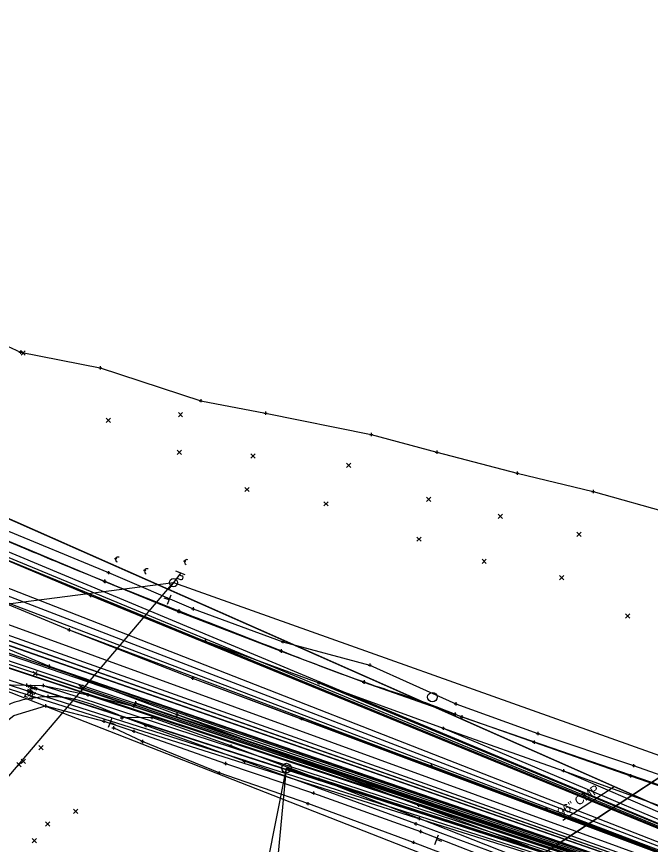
# Model space of a CAD drawing. Extents: x 2331247 to 2333939, y 279314 to 282014.
# Drawn here: x 2332530.2 to 2332730.7, y 280536.5 to 280798.3 of the extents above; entities that cross this region are included whole.
import ezdxf

# ---------------------------------------------------------------- set-up
doc = ezdxf.new("R2010")
doc.units = 0
for name, color, linetype in [('DR_X_Storm_Sewer', 7, 'Continuous'), ('DR_X_Text', 7, 'Continuous'), ('PF_X_Ground_Line', 7, 'Continuous'), ('PV_X_COP', 7, 'Continuous'), ('PV_X_EOP', 7, 'Continuous'), ('PV_X_Shoulder_Aggregate', 7, 'Continuous'), ('RD_X_Cells', 7, 'Continuous'), ('RD_X_GR_Lt', 7, 'Continuous'), ('RW_X_Esmt_SH', 7, 'Continuous'), ('RW_X_Fee_RW', 7, 'Continuous'), ('Stream 1', 7, 'Continuous'), ('SV_Observation', 7, 'Continuous'), ('SV_Setup', 7, 'Continuous'), ('SV_X_Break_Lines', 7, 'Continuous'), ('SV_X_Random_Point', 7, 'Continuous'), ('UT_X_Overhead_Combined', 7, 'Continuous'), ('UT_X_Overhead_Telecom', 7, 'Continuous')]:
    doc.layers.add(name, color=color, linetype=linetype)

msp = doc.modelspace()

# ---------------------------------------------------------------- linework, layer by layer
msp.add_lwpolyline([(2332817.33, 280612.66), (2332607.42, 280474.92)])
at = {"layer": 'DR_X_Storm_Sewer'}
msp.add_line((2332607.42, 280474.92), (2332817.33, 280612.66), dxfattribs=at)
at = {"layer": 'DR_X_Text'}
msp.add_line((2332719.22, 280554.74), (2332702.94, 280544.06), dxfattribs=at)
at = {"layer": 'PF_X_Ground_Line'}
for centre in [(2332661.71, 280583.06), (2332615.53, 280560.63)]:
    msp.add_circle(centre, 1.5, dxfattribs=at)
at = {"layer": 'PV_X_COP'}
msp.add_lwpolyline([(2332444.16, 280650.15), (2332476.96, 280634.44), (2332513.29, 280618.27), (2332546.76, 280604.36), (2332585.85, 280589.05), (2332620.3, 280576.24), (2332661.35, 280561.33), (2332697.65, 280547.71), (2332730.35, 280535.78)], dxfattribs=at)
at = {"layer": 'PV_X_EOP'}
for points in [[(2332450.46, 280661.19), (2332482.6, 280645.87), (2332517.32, 280630.52), (2332553.59, 280615.18), (2332589.86, 280600.74), (2332625.75, 280587.6), (2332665.17, 280573.2), (2332703.16, 280559.78), (2332734.66, 280548.38), (2332773.04, 280534.85)], [(2332438.33, 280638.42), (2332471.73, 280622.52), (2332488.1, 280614.88), (2332507.93, 280606.44), (2332540.43, 280592.84), (2332580.91, 280577.56), (2332615.81, 280564.58), (2332657.37, 280548.85), (2332692.15, 280535.94)], [(2332488.15, 280614.77), (2332487.52, 280613.4), (2332492.44, 280608.51), (2332496.3, 280602.83), (2332499.57, 280597.56), (2332513.01, 280591.6), (2332523.6, 280587.02), (2332533.28, 280586.84), (2332538.59, 280586.73), (2332552.7, 280583.8), (2332567.15, 280580.24), (2332567.76, 280581.26)]]:
    msp.add_lwpolyline(points, dxfattribs=at)
at = {"layer": 'PV_X_Shoulder_Aggregate'}
msp.add_lwpolyline([(2332687.13, 280533.02), (2332657.51, 280544.64), (2332625.77, 280557.07), (2332597.93, 280567.61), (2332572.94, 280576.61), (2332563.48, 280576.47)], dxfattribs=at)
at = {"layer": 'RD_X_Cells'}
for p, q in [((2332533.78, 280585.61), (2332533.39, 280584.69)), ((2332534.71, 280584.67), (2332534.71, 280584.67)), ((2332536.04, 280584.68), (2332535.65, 280583.75))]:
    msp.add_line(p, q, dxfattribs=at)
for points in [[(2332533.98, 280586.09), (2332534.35, 280586.99), (2332535.25, 280586.62)], [(2332533.71, 280582.92), (2332532.81, 280583.3), (2332533.2, 280584.21)], [(2332534.38, 280583.7), (2332534.42, 280583.62), (2332534.44, 280583.57), (2332534.46, 280583.53), (2332534.48, 280583.51), (2332534.52, 280583.47), (2332534.55, 280583.44), (2332534.62, 280583.39), (2332534.65, 280583.37), (2332534.7, 280583.35), (2332534.78, 280583.34), (2332534.84, 280583.33), (2332534.9, 280583.35), (2332534.97, 280583.39), (2332535.02, 280583.43), (2332535.04, 280583.44), (2332535.09, 280583.49), (2332535.32, 280584.06), (2332533.85, 280584.68), (2332533.58, 280584.04), (2332533.59, 280583.94), (2332533.62, 280583.84), (2332533.69, 280583.75), (2332533.78, 280583.67), (2332533.88, 280583.61), (2332533.95, 280583.58), (2332534.03, 280583.58), (2332534.15, 280583.58), (2332534.25, 280583.61), (2332534.38, 280583.7), (2332534.65, 280584.34)], [(2332534.47, 280586.18), (2332535.95, 280585.56), (2332534.25, 280585.64), (2332535.51, 280584.52), (2332534.03, 280585.13)], [(2332535.71, 280586.42), (2332536.61, 280586.05), (2332536.23, 280585.16)], [(2332535.45, 280583.27), (2332535.07, 280582.36), (2332534.18, 280582.73)]]:
    msp.add_lwpolyline(points, dxfattribs=at)
at = {"layer": 'RD_X_GR_Lt'}
for p, q in [((2332671, 280576.81), (2332757.54, 280546.99)), ((2332602.3, 280562.78), (2332571.04, 280574.11)), ((2332656.5, 280542.97), (2332602.3, 280562.78)), ((2332719.13, 280519.92), (2332656.5, 280542.97))]:
    msp.add_line(p, q, dxfattribs=at)
for points in [[(2332284.04, 280768.15), (2332290.4, 280762.4), (2332306.51, 280748.93), (2332330.87, 280733.26), (2332354.16, 280719.6), (2332375.56, 280706.62), (2332399.69, 280693.06), (2332427.39, 280678.53), (2332457.23, 280663.43), (2332489.53, 280649.05), (2332523.64, 280633.83), (2332554.34, 280621.11), (2332584.43, 280609.19), (2332611.78, 280598.56), (2332640.76, 280587.24), (2332660.26, 280581.49), (2332670.28, 280577.06), (2332671, 280576.81)], [(2332571.04, 280574.11), (2332559.55, 280578.28), (2332546.93, 280585.22), (2332522.34, 280581.21), (2332514.24, 280566.6), (2332508.9, 280557.77), (2332507.36, 280555.09)]]:
    msp.add_open_spline(points, degree=3, dxfattribs=at)
at = {"layer": 'RW_X_Esmt_SH'}
for p, q in [((2332582.02, 280622.27), (2332578.33, 280617.27)), ((2332583.51, 280621.69), (2332580.53, 280622.86)), ((2332580.87, 280620.71), (2332581.98, 280620.27)), ((2332581.65, 280621.77), (2332582.44, 280621.46))]:
    msp.add_line(p, q, dxfattribs=at)
for centre, radius in [((2332561.54, 280626.86), 0.2), ((2332583.34, 280626.05), 0.2), ((2332570.72, 280623.14), 0.2), ((2332579.81, 280619.27), 1.3)]:
    msp.add_circle(centre, radius, dxfattribs=at)
for centre, radius, start, end in [((2332562.28, 280626.56), 0.8, 67.9895, 247.9895), ((2332584.09, 280625.76), 0.8, 68.5702, 248.5702), ((2332571.46, 280622.85), 0.8, 68.2799, 248.2799), ((2332582.22, 280620.86), 0.638, 247.4256, 69.6722)]:
    msp.add_arc(centre, radius, start, end, dxfattribs=at)
at = {"layer": 'RW_X_Fee_RW'}
for p, q in [((2332578.97, 280615.29), (2332577.81, 280612.31)), ((2332578.39, 280613.8), (2332576.9, 280614.38)), ((2332559.26, 280573.52), (2332560.43, 280576.49)), ((2332559.85, 280575.01), (2332561.34, 280574.42)), ((2332662.54, 280536.5), (2332663.63, 280539.51)), ((2332663.09, 280538), (2332664.59, 280537.46))]:
    msp.add_line(p, q, dxfattribs=at)
at = {"layer": 'Stream 1'}
for p, q in [((2332530.87, 280692.17), (2332531.87, 280692.17)), ((2332531.37, 280692.67), (2332531.37, 280691.67)), ((2332531.37, 280692.17), (2332531.37, 280692.17)), ((2332556.16, 280687.23), (2332557.16, 280687.23)), ((2332556.66, 280687.73), (2332556.66, 280686.73)), ((2332556.66, 280687.23), (2332556.66, 280687.23)), ((2332587.92, 280676.82), (2332588.92, 280676.82)), ((2332588.42, 280677.32), (2332588.42, 280676.32)), ((2332588.42, 280676.82), (2332588.42, 280676.82)), ((2332608.42, 280672.87), (2332609.42, 280672.87)), ((2332608.92, 280673.37), (2332608.92, 280672.37)), ((2332608.92, 280672.87), (2332608.92, 280672.87)), ((2332641.85, 280666.14), (2332642.85, 280666.14)), ((2332642.35, 280666.64), (2332642.35, 280665.64)), ((2332642.35, 280666.14), (2332642.35, 280666.14)), ((2332662.58, 280660.52), (2332663.58, 280660.52)), ((2332663.08, 280661.02), (2332663.08, 280660.02)), ((2332663.08, 280660.52), (2332663.08, 280660.52)), ((2332688.08, 280653.89), (2332689.08, 280653.89)), ((2332688.58, 280654.39), (2332688.58, 280653.39)), ((2332688.58, 280653.89), (2332688.58, 280653.89)), ((2332712.04, 280648.12), (2332713.04, 280648.12)), ((2332712.54, 280648.62), (2332712.54, 280647.62)), ((2332712.54, 280648.12), (2332712.54, 280648.12)), ((2332558.71, 280622.43), (2332559.71, 280622.43)), ((2332559.21, 280622.93), (2332559.21, 280621.93)), ((2332559.21, 280622.43), (2332559.21, 280622.43)), ((2332557.48, 280619.72), (2332558.48, 280619.72)), ((2332557.6, 280619.63), (2332558.6, 280619.63)), ((2332557.98, 280620.22), (2332557.98, 280619.22)), ((2332557.98, 280619.72), (2332557.98, 280619.72)), ((2332558.1, 280620.13), (2332558.1, 280619.13)), ((2332558.1, 280619.63), (2332558.1, 280619.63)), ((2332553.59, 280615.68), (2332553.59, 280614.68)), ((2332553.09, 280615.18), (2332554.09, 280615.18)), ((2332553.59, 280615.18), (2332553.59, 280615.18)), ((2332580.97, 280610.09), (2332581.97, 280610.09)), ((2332581.02, 280610.37), (2332582.02, 280610.37)), ((2332581.47, 280610.59), (2332581.47, 280609.59)), ((2332581.47, 280610.09), (2332581.47, 280610.09)), ((2332581.52, 280610.87), (2332581.52, 280609.87)), ((2332581.52, 280610.37), (2332581.52, 280610.37)), ((2332585.49, 280611), (2332586.49, 280611)), ((2332585.99, 280611.5), (2332585.99, 280610.5)), ((2332585.99, 280611), (2332585.99, 280611)), ((2332546.76, 280604.86), (2332546.76, 280603.86)), ((2332546.26, 280604.36), (2332547.26, 280604.36)), ((2332546.76, 280604.36), (2332546.76, 280604.36)), ((2332589.36, 280600.74), (2332590.36, 280600.74)), ((2332589.86, 280601.24), (2332589.86, 280600.24)), ((2332589.86, 280600.74), (2332589.86, 280600.74)), ((2332613.92, 280600.59), (2332614.92, 280600.59)), ((2332614.42, 280601.09), (2332614.42, 280600.09)), ((2332614.42, 280600.59), (2332614.42, 280600.59)), ((2332613.37, 280597.73), (2332614.37, 280597.73)), ((2332613.39, 280597.55), (2332614.39, 280597.55)), ((2332613.87, 280598.23), (2332613.87, 280597.23)), ((2332613.87, 280597.73), (2332613.87, 280597.73)), ((2332613.89, 280598.05), (2332613.89, 280597.05)), ((2332613.89, 280597.55), (2332613.89, 280597.55)), ((2332539.93, 280592.84), (2332540.93, 280592.84)), ((2332540.43, 280593.34), (2332540.43, 280592.34)), ((2332540.43, 280592.84), (2332540.43, 280592.84)), ((2332641.42, 280593.2), (2332642.42, 280593.2)), ((2332641.92, 280593.7), (2332641.92, 280592.7)), ((2332641.92, 280593.2), (2332641.92, 280593.2)), ((2332585.85, 280589.55), (2332585.85, 280588.55)), ((2332532.78, 280586.84), (2332533.78, 280586.84)), ((2332533.28, 280587.34), (2332533.28, 280586.34)), ((2332533.28, 280586.84), (2332533.28, 280586.84)), ((2332538.09, 280586.73), (2332539.09, 280586.73)), ((2332538.59, 280587.23), (2332538.59, 280586.23)), ((2332538.59, 280586.73), (2332538.59, 280586.73)), ((2332585.35, 280589.05), (2332586.35, 280589.05)), ((2332585.85, 280589.05), (2332585.85, 280589.05)), ((2332625.25, 280587.6), (2332626.25, 280587.6)), ((2332625.75, 280588.1), (2332625.75, 280587.1)), ((2332625.75, 280587.6), (2332625.75, 280587.6)), ((2332639.55, 280587.76), (2332640.55, 280587.76)), ((2332639.6, 280587.91), (2332640.6, 280587.91)), ((2332640.05, 280588.26), (2332640.05, 280587.26)), ((2332640.05, 280587.76), (2332640.05, 280587.76)), ((2332640.1, 280588.41), (2332640.1, 280587.41)), ((2332640.1, 280587.91), (2332640.1, 280587.91)), ((2332552.7, 280584.3), (2332552.7, 280583.3)), ((2332539.6, 280583.27), (2332540.6, 280583.27)), ((2332540.1, 280583.77), (2332540.1, 280582.77)), ((2332540.1, 280583.27), (2332540.1, 280583.27)), ((2332552.2, 280583.8), (2332553.2, 280583.8)), ((2332552.7, 280583.8), (2332552.7, 280583.8)), ((2332567.26, 280581.26), (2332568.26, 280581.26)), ((2332567.76, 280581.76), (2332567.76, 280580.76)), ((2332567.76, 280581.26), (2332567.76, 280581.26)), ((2332669.09, 280581.42), (2332669.09, 280580.42)), ((2332538.86, 280580.31), (2332539.86, 280580.31)), ((2332539.36, 280580.81), (2332539.36, 280579.81)), ((2332539.36, 280580.31), (2332539.36, 280580.31)), ((2332566.65, 280580.24), (2332567.65, 280580.24)), ((2332567.15, 280580.74), (2332567.15, 280579.74)), ((2332567.15, 280580.24), (2332567.15, 280580.24)), ((2332668.59, 280580.92), (2332669.59, 280580.92)), ((2332669.09, 280580.92), (2332669.09, 280580.92)), ((2332562.98, 280576.47), (2332563.98, 280576.47)), ((2332563.48, 280576.97), (2332563.48, 280575.97)), ((2332563.48, 280576.47), (2332563.48, 280576.47)), ((2332572.44, 280576.61), (2332573.44, 280576.61)), ((2332572.94, 280577.11), (2332572.94, 280576.11)), ((2332572.94, 280576.61), (2332572.94, 280576.61)), ((2332580.41, 280577.56), (2332581.41, 280577.56)), ((2332580.91, 280578.06), (2332580.91, 280577.06)), ((2332580.91, 280577.56), (2332580.91, 280577.56)), ((2332619.8, 280576.24), (2332620.8, 280576.24)), ((2332620.3, 280576.74), (2332620.3, 280575.74)), ((2332620.3, 280576.24), (2332620.3, 280576.24)), ((2332668.3, 280577.64), (2332669.3, 280577.64)), ((2332668.38, 280577.67), (2332669.38, 280577.67)), ((2332668.8, 280578.14), (2332668.8, 280577.14)), ((2332668.8, 280577.64), (2332668.8, 280577.64)), ((2332668.88, 280578.17), (2332668.88, 280577.17)), ((2332668.88, 280577.67), (2332668.88, 280577.67)), ((2332670.5, 280576.81), (2332671.5, 280576.81)), ((2332671, 280577.31), (2332671, 280576.31)), ((2332671, 280576.81), (2332671, 280576.81)), ((2332557.26, 280575.46), (2332558.26, 280575.46)), ((2332557.76, 280575.96), (2332557.76, 280574.96)), ((2332557.76, 280575.46), (2332557.76, 280575.46)), ((2332560.81, 280573.85), (2332560.81, 280572.85)), ((2332570.54, 280574.11), (2332571.54, 280574.11)), ((2332571.04, 280574.61), (2332571.04, 280573.61)), ((2332571.04, 280574.11), (2332571.04, 280574.11)), ((2332665.17, 280573.7), (2332665.17, 280572.7)), ((2332560.31, 280573.35), (2332561.31, 280573.35)), ((2332560.81, 280573.35), (2332560.81, 280573.35)), ((2332566.73, 280572.25), (2332567.73, 280572.25)), ((2332567.23, 280572.75), (2332567.23, 280571.75)), ((2332567.23, 280572.25), (2332567.23, 280572.25)), ((2332664.67, 280573.2), (2332665.67, 280573.2)), ((2332665.17, 280573.2), (2332665.17, 280573.2)), ((2332694.57, 280571.58), (2332695.57, 280571.58)), ((2332695.07, 280572.08), (2332695.07, 280571.08)), ((2332695.07, 280571.58), (2332695.07, 280571.58)), ((2332569.5, 280569.04), (2332570.5, 280569.04)), ((2332570, 280569.54), (2332570, 280568.54)), ((2332570, 280569.04), (2332570, 280569.04)), ((2332693.41, 280568.82), (2332694.41, 280568.82)), ((2332693.91, 280569.32), (2332693.91, 280568.32)), ((2332693.91, 280568.82), (2332693.91, 280568.82)), ((2332597.43, 280567.61), (2332598.43, 280567.61)), ((2332597.93, 280568.11), (2332597.93, 280567.11)), ((2332597.93, 280567.61), (2332597.93, 280567.61)), ((2332602.3, 280563.28), (2332602.3, 280562.28)), ((2332615.31, 280564.58), (2332616.31, 280564.58)), ((2332615.81, 280565.08), (2332615.81, 280564.08)), ((2332615.81, 280564.58), (2332615.81, 280564.58)), ((2332595.77, 280562.06), (2332596.77, 280562.06)), ((2332596.27, 280562.56), (2332596.27, 280561.56)), ((2332596.27, 280562.06), (2332596.27, 280562.06)), ((2332601.8, 280562.78), (2332602.8, 280562.78)), ((2332602.3, 280562.78), (2332602.3, 280562.78)), ((2332660.85, 280561.33), (2332661.85, 280561.33)), ((2332661.35, 280561.83), (2332661.35, 280560.83)), ((2332661.35, 280561.33), (2332661.35, 280561.33)), ((2332724.88, 280561.4), (2332725.88, 280561.4)), ((2332725.38, 280561.9), (2332725.38, 280560.9)), ((2332725.38, 280561.4), (2332725.38, 280561.4)), ((2332593.81, 280559.08), (2332594.81, 280559.08)), ((2332594.31, 280559.58), (2332594.31, 280558.58)), ((2332594.31, 280559.08), (2332594.31, 280559.08)), ((2332702.66, 280559.78), (2332703.66, 280559.78)), ((2332703.16, 280560.28), (2332703.16, 280559.28)), ((2332703.16, 280559.78), (2332703.16, 280559.78)), ((2332723.92, 280558.17), (2332724.92, 280558.17)), ((2332724.42, 280558.67), (2332724.42, 280557.67)), ((2332724.42, 280558.17), (2332724.42, 280558.17)), ((2332625.27, 280557.07), (2332626.27, 280557.07)), ((2332625.77, 280557.57), (2332625.77, 280556.57)), ((2332625.77, 280557.07), (2332625.77, 280557.07)), ((2332623.58, 280552.73), (2332624.58, 280552.73)), ((2332624.08, 280553.23), (2332624.08, 280552.23)), ((2332624.08, 280552.73), (2332624.08, 280552.73)), ((2332622.31, 280549.89), (2332622.31, 280548.89)), ((2332621.81, 280549.39), (2332622.81, 280549.39)), ((2332622.31, 280549.39), (2332622.31, 280549.39)), ((2332656.87, 280548.85), (2332657.87, 280548.85)), ((2332657.37, 280549.35), (2332657.37, 280548.35)), ((2332657.37, 280548.85), (2332657.37, 280548.85)), ((2332697.15, 280547.71), (2332698.15, 280547.71)), ((2332697.65, 280548.21), (2332697.65, 280547.21)), ((2332697.65, 280547.71), (2332697.65, 280547.71)), ((2332657.01, 280544.64), (2332658.01, 280544.64)), ((2332657.51, 280545.14), (2332657.51, 280544.14)), ((2332657.51, 280544.64), (2332657.51, 280544.64)), ((2332656, 280542.97), (2332657, 280542.97)), ((2332656.5, 280543.47), (2332656.5, 280542.47)), ((2332656.5, 280542.97), (2332656.5, 280542.97)), ((2332657.49, 280540.58), (2332658.49, 280540.58)), ((2332657.99, 280541.08), (2332657.99, 280540.08)), ((2332657.99, 280540.58), (2332657.99, 280540.58)), ((2332655.24, 280537.12), (2332656.24, 280537.12)), ((2332655.74, 280537.62), (2332655.74, 280536.62)), ((2332655.74, 280537.12), (2332655.74, 280537.12))]:
    msp.add_line(p, q, dxfattribs=at)
at = {"layer": 'SV_Observation'}
for p, q in [((2332168.11, 280798.3), (2332955.23, 280450.49)), ((2332450.46, 280661.19), (2332955.23, 280450.49)), ((2332444.16, 280650.15), (2332955.23, 280450.49)), ((2332482.6, 280645.87), (2332955.23, 280450.49)), ((2332438.33, 280638.42), (2332955.23, 280450.49)), ((2332476.96, 280634.44), (2332955.23, 280450.49)), ((2332517.32, 280630.52), (2332955.23, 280450.49)), ((2332471.73, 280622.52), (2332955.23, 280450.49)), ((2332513.29, 280618.27), (2332955.23, 280450.49)), ((2332487.52, 280613.4), (2332955.23, 280450.49)), ((2332488.1, 280614.88), (2332955.23, 280450.49)), ((2332488.15, 280614.77), (2332955.23, 280450.49)), ((2332553.59, 280615.18), (2332955.23, 280450.49)), ((2332492.44, 280608.51), (2332955.23, 280450.49)), ((2332496.83, 280607.57), (2332955.23, 280450.49)), ((2332507.93, 280606.44), (2332955.23, 280450.49)), ((2332496.3, 280602.83), (2332955.23, 280450.49)), ((2332546.76, 280604.36), (2332955.23, 280450.49)), ((2332506.21, 280601.78), (2332955.23, 280450.49)), ((2332589.86, 280600.74), (2332955.23, 280450.49)), ((2332499.57, 280597.56), (2332955.23, 280450.49)), ((2332515.9, 280597.39), (2332955.23, 280450.49)), ((2332526.22, 280592.74), (2332955.23, 280450.49)), ((2332540.43, 280592.84), (2332955.23, 280450.49)), ((2332513.01, 280591.6), (2332955.23, 280450.49)), ((2332536.02, 280590.54), (2332955.23, 280450.49)), ((2332523.6, 280587.02), (2332955.23, 280450.49)), ((2332533.28, 280586.84), (2332955.23, 280450.49)), ((2332538.59, 280586.73), (2332955.23, 280450.49)), ((2332585.85, 280589.05), (2332955.23, 280450.49)), ((2332625.75, 280587.6), (2332955.23, 280450.49)), ((2332550.52, 280586.33), (2332955.23, 280450.49)), ((2332552.7, 280583.8), (2332955.23, 280450.49)), ((2332567.76, 280581.26), (2332955.23, 280450.49)), ((2332567.15, 280580.24), (2332955.23, 280450.49)), ((2332580.91, 280577.56), (2332955.23, 280450.49)), ((2332620.3, 280576.24), (2332955.23, 280450.49)), ((2332665.17, 280573.2), (2332955.23, 280450.49)), ((2332615.81, 280564.58), (2332955.23, 280450.49)), ((2332597.8, 280471.17), (2332615.53, 280560.63)), ((2332607.42, 280474.92), (2332615.53, 280560.63)), ((2332615.53, 280560.63), (2332955.23, 280450.49)), ((2332955.23, 280450.5), (2332615.53, 280560.63)), ((2332661.35, 280561.33), (2332955.23, 280450.49)), ((2332703.16, 280559.78), (2332955.23, 280450.49)), ((2332657.37, 280548.85), (2332955.23, 280450.49)), ((2332697.65, 280547.71), (2332955.23, 280450.49))]:
    msp.add_line(p, q, dxfattribs=at)
at = {"layer": 'SV_Setup'}
for p, q in [((2332955.23, 280450.49), (2332168.1, 280798.3)), ((2332615.53, 280560.63), (2332955.23, 280450.49))]:
    msp.add_line(p, q, dxfattribs=at)
at = {"layer": 'SV_X_Break_Lines'}
for points in [[(2332334.94, 280730.96), (2332355.04, 280718.78), (2332372.38, 280708.63), (2332399.72, 280693.04), (2332427.42, 280678.36), (2332455.4, 280664.53), (2332489.33, 280649.12), (2332523.25, 280634.23), (2332558.1, 280619.63), (2332581.47, 280610.09), (2332613.89, 280597.55), (2332640.05, 280587.76), (2332668.8, 280577.64), (2332693.91, 280568.82), (2332724.42, 280558.17), (2332748.74, 280549.71), (2332770.52, 280541.76), (2332798.34, 280531.25)], [(2332342.93, 280729.06), (2332360.86, 280718.71), (2332371.5, 280712.31), (2332400.86, 280695.93), (2332429.58, 280680.84), (2332456.55, 280667.58), (2332490.57, 280652), (2332524.45, 280636.78), (2332559.21, 280622.43), (2332585.99, 280611), (2332614.42, 280600.59), (2332641.92, 280593.2), (2332669.09, 280580.92), (2332695.07, 280571.58), (2332725.38, 280561.4), (2332749.78, 280552.83), (2332772.2, 280545.01), (2332799.94, 280535)], [(2332506.58, 280703.5), (2332531.37, 280692.17), (2332556.66, 280687.23), (2332588.42, 280676.82), (2332608.92, 280672.87), (2332642.35, 280666.14), (2332663.08, 280660.52), (2332688.58, 280653.89), (2332712.54, 280648.12), (2332737.33, 280641.17), (2332759.6, 280635), (2332774.98, 280633.37), (2332782.41, 280632.18), (2332785.19, 280632.94), (2332786.5, 280633.83), (2332787.84, 280635.06), (2332795.38, 280637.5), (2332821.18, 280642.63), (2332843.65, 280644.3), (2332859.63, 280646.82)], [(2332489.91, 280516.98), (2332502.66, 280538.92), (2332514.4, 280560.4), (2332522.01, 280571.56), (2332529.27, 280577.21), (2332539.36, 280580.31), (2332557.76, 280575.46), (2332567.23, 280572.25), (2332596.27, 280562.06), (2332624.08, 280552.73), (2332657.99, 280540.58), (2332687.22, 280529.22)], [(2332714.55, 280517.22), (2332692.61, 280522.97), (2332655.74, 280537.12), (2332622.31, 280549.39), (2332594.31, 280559.08), (2332570, 280569.04), (2332560.81, 280573.35)]]:
    msp.add_lwpolyline(points, dxfattribs=at)
at = {"layer": 'SV_X_Random_Point'}
for p, q in [((2332531.59, 280691.21), (2332532.93, 280692.55)), ((2332531.59, 280692.55), (2332532.93, 280691.21)), ((2332581.38, 280671.75), (2332582.71, 280673.09)), ((2332581.38, 280673.09), (2332582.71, 280671.75)), ((2332558.55, 280669.93), (2332559.89, 280671.27)), ((2332558.55, 280671.27), (2332559.89, 280669.93)), ((2332580.97, 280659.78), (2332582.3, 280661.12)), ((2332580.97, 280661.12), (2332582.3, 280659.78)), ((2332604.28, 280658.64), (2332605.61, 280659.97)), ((2332604.28, 280659.97), (2332605.61, 280658.64)), ((2332634.59, 280655.7), (2332635.92, 280657.04)), ((2332634.59, 280657.04), (2332635.92, 280655.7)), ((2332602.41, 280648.05), (2332603.74, 280649.39)), ((2332602.41, 280649.39), (2332603.74, 280648.05)), ((2332627.39, 280643.51), (2332628.73, 280644.85)), ((2332627.39, 280644.85), (2332628.73, 280643.51)), ((2332659.88, 280644.95), (2332661.21, 280646.29)), ((2332659.88, 280646.29), (2332661.21, 280644.95)), ((2332682.53, 280639.59), (2332683.86, 280640.93)), ((2332682.53, 280640.93), (2332683.86, 280639.59)), ((2332656.83, 280632.34), (2332658.16, 280633.68)), ((2332656.83, 280633.68), (2332658.16, 280632.34)), ((2332707.44, 280633.85), (2332708.77, 280635.19)), ((2332707.44, 280635.19), (2332708.77, 280633.85)), ((2332677.44, 280625.32), (2332678.77, 280626.65)), ((2332677.44, 280626.65), (2332678.77, 280625.32)), ((2332701.93, 280620.21), (2332703.26, 280621.55)), ((2332701.93, 280621.55), (2332703.26, 280620.21)), ((2332722.85, 280608.02), (2332724.18, 280609.36)), ((2332722.85, 280609.36), (2332724.18, 280608.02)), ((2332535.36, 280589.87), (2332536.69, 280591.21)), ((2332535.36, 280591.21), (2332536.69, 280589.87)), ((2332549.86, 280585.66), (2332551.19, 280586.99)), ((2332549.86, 280586.99), (2332551.19, 280585.66)), ((2332537.25, 280566.41), (2332538.58, 280567.75)), ((2332537.25, 280567.75), (2332538.58, 280566.41)), ((2332531.63, 280562.06), (2332532.97, 280563.39)), ((2332531.63, 280563.39), (2332532.97, 280562.06)), ((2332530.28, 280561.03), (2332531.61, 280562.36)), ((2332530.28, 280562.36), (2332531.61, 280561.03)), ((2332548.18, 280546.28), (2332549.51, 280547.61)), ((2332548.18, 280547.61), (2332549.51, 280546.28)), ((2332539.32, 280542.24), (2332540.65, 280543.58)), ((2332539.32, 280543.58), (2332540.65, 280542.24)), ((2332535.14, 280537.03), (2332536.48, 280538.36)), ((2332535.14, 280538.36), (2332536.48, 280537.03))]:
    msp.add_line(p, q, dxfattribs=at)
at = {"layer": 'UT_X_Overhead_Combined'}
msp.add_line((2332579.81, 280619.27), (2332737.79, 280563.05), dxfattribs=at)
msp.add_lwpolyline([(2332212.16, 280757.54), (2332474.12, 280605.71), (2332579.81, 280619.27)], dxfattribs=at)
at = {"layer": 'UT_X_Overhead_Telecom'}
msp.add_line((2332478.1, 280499.82), (2332579.81, 280619.27), dxfattribs=at)
msp.add_lwpolyline([(2332474.12, 280605.71), (2332735.57, 280503.33), (2332947.92, 280387.93), (2333091.98, 280195.88)], dxfattribs=at)

# ---------------------------------------------------------------- texts
at = {"layer": 'DR_X_Text'}
msp.add_text('96" CMP', height=2.8, rotation=33.2733, dxfattribs=at).set_placement((2332702.43, 280545.04))

doc.saveas('drawing.dxf')
